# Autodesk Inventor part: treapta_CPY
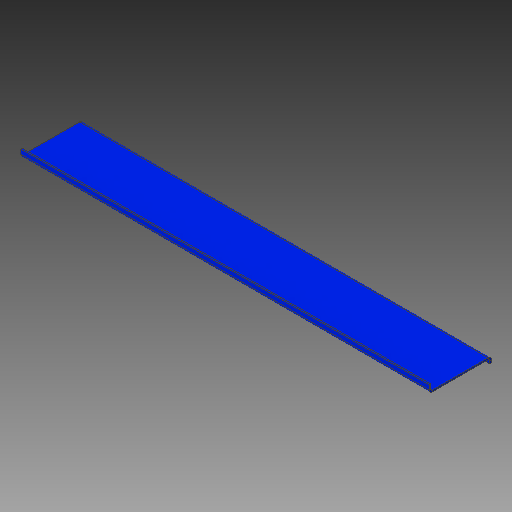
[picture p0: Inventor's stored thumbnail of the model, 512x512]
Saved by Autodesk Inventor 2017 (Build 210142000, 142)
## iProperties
Created: 2017-11
Part Number: treapta_CPY
Material: Generic
Document SubType Name: Sheet Metal
Designer: iusti
Density: 1 g/cm^3
Sheet Metal Rule: Default_mm
Appearance: Default
Author: iusti
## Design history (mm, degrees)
node "Contour Flange1"
  sketch "Sketch1"
    geometry: L1 (20.807, 182.422)-(0.807, 182.422); L2 (0.807, 182.422)-(0.807, -17.578); L3 (0.807, -17.578)-(-19.193, -17.578); 1 further point
    constraints: 6 end point, 2 perpendicular, 1 horizontal
    dimensions: "d0" = 20 distance of L1.start L1.end; "d1" = 20 distance of L2.end L3.end; "d2" = 200 distance of L1.end L2.end
body "Solid1"
face "Plate1" dims "d3" = 5 (= BendReliefWidth), "d4" = 2.5 (= BendReliefDepth), "d5" = 10 (= MinimumRemnant), "d6" = 5 (= BendRadius), "d7" = 1350, "d8" = 5 (= BendRadius), "d9" = 0.5, "d10" = 20 (= CornerReliefSize), "d11" = 5 (= GapSize), "d12" = 5 (= JacobiRadiusSize), "SeamGap" = 0.01, "Thickness" = 5 (derived)
bend "Bend1" dims "d3" = 5 (= BendReliefWidth), "d4" = 2.5 (= BendReliefDepth), "d5" = 10 (= MinimumRemnant), "d6" = 5 (= BendRadius), "d8" = 5 (= BendRadius), "d9" = 0.5, "SeamGap" = 0.01, "Thickness" = 5 (derived)
feature "Corner1" dims "d9" = 0.5, "d10" = 20 (= CornerReliefSize), "d11" = 5 (= GapSize), "d12" = 5 (= JacobiRadiusSize)
other parameters: "BendRadius" = 5 (= Thickness), "BendReliefWidth" = 5 (= Thickness), "BendReliefDepth" = 2.5 (= 0.5 x Thickness), "TransitionRadius" = 5 (= BendRadius), "JacobiRadiusSize" = 5 (= BendRadius), "GapSize" = 5 (= Thickness)
